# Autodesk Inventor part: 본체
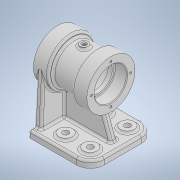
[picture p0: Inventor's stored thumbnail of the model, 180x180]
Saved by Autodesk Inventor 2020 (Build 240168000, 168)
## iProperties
Created: 2024-02
Part Number: 본체
Material: 일반
Document SubType Name: Modeling
Designer: oem
Density: 1 g/cm^3
Appearance: 기본값
Author: oem
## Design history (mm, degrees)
sketch "스케치1"
  geometry: L1 (0, 0)-(22, 0); L2 (22, 0)-(22, 35); L3 (22, 35)-(0, 35); L4 (0, 35)-(0, 0); L5 (22, 0)-(56, 0); L6 (56, 0)-(56, 28.5); L7 (56, 28.5)-(22, 28.5); L8 (22, 28.5)-(22, 0); L9 (56, 0)-(78, 0); L10 (78, 0)-(78, 35); L11 (78, 35)-(56, 35); L12 (56, 35)-(56, 0); 2 further points
  constraints: 24 end point, 6 parallel, 3 horizontal, 3 perpendicular, 1 point on line
  dimensions: "d0" = 70 diameter of L3 L1; "d1" = 57 diameter of L7 L5; "d2" = 22 distance of L2.end L3.end; "d3" = 22 distance of L10.end L11.end; "d4" = 78 distance between parallel lines of L10 L4
revolve "회전1" sketch "스케치1" stored, may be unused: angle "d5" = 90 deg
sketch "스케치2"
  geometry: L1 (0, -35)-(0, 35) reference; L2 (78, -35)-(78, 35) reference; L3 (0, 0)-(18, 0); L4 (18, 0)-(18, 23.5); L5 (18, 23.5)-(0, 23.5); L6 (0, 23.5)-(0, 0); L7 (18, 0)-(24, 0); L8 (24, 0)-(24, 20); L9 (24, 20)-(18, 20); L10 (18, 20)-(18, 0); L11 (24, 0)-(54, 0); L12 (54, 0)-(54, 23.5); L13 (54, 23.5)-(24, 23.5); L14 (24, 23.5)-(24, 0); L15 (54, 0)-(60, 0); L16 (60, 0)-(60, 20); L17 (60, 20)-(54, 20); L18 (54, 20)-(54, 0); L19 (60, 0)-(78, 0); L20 (78, 0)-(78, 23.5); L21 (78, 23.5)-(60, 23.5); L22 (60, 23.5)-(60, 0); 6 further points
  constraints: 40 end point, 10 parallel, 5 horizontal, 5 perpendicular, 3 point on line
  dimensions: "d6" = 47 diameter of L5 L3; "d7" = 40 diameter of L9 L7; "d8" = 47 diameter of L13 L11; "d9" = 18 distance of L4.end L5.end; "d10" = 18 distance of L20.end L21.end; "d11" = 24 distance between parallel lines of L8 L1; "d12" = 24 distance between parallel lines of L18 L2
revolve "회전2" sketch "스케치2" stored, may be unused: angle "d13" = 90 deg
node "작업 평면1"
sketch "스케치3"
  geometry: L1 (0, 35)-(0, -35) reference; L2 (-5, -47)-(-95, -47); L3 (-95, -47)-(-95, 47); L4 (-95, 47)-(-5, 47); L5 (-5, 47)-(-5, -47); 1 further point
  constraints: 8 end point, 2 parallel, 1 horizontal, 1 perpendicular
  dimensions: "d15" = 5 distance between parallel lines of L5 L1; "d16" = 90 distance between parallel lines of L3 L5; "d17" = 47 distance from line of L4 point (0, 0); "d18" = 94 distance of L2.end L3.end
extrude "돌출1" join sketch "스케치3" distance "d19" = 10; taper "d20" = 0 deg
sketch "스케치6"
  geometry: L1 (0, 10)-(94, 10) reference; L2 (8, 10)-(12.055, 81.969); L3 (86, 10)-(81.945, 81.969); L4 (8, 10)-(86, 10); 4 further points
  constraints: 6 end point, 2 point on line, 1 horizontal, 6 other
  dimensions: "d24" = 8 distance of L2.start L1.start; "d25" = 8 distance of L3.start L1.end
extrude "돌출2" join sketch "스케치6" distance "d26" = 10; taper "d27" = 0 deg
sketch "스케치7"
  geometry: L1 (95, -70)-(5, -70) reference; L2 (83, -70)-(66.656, -25.096); L3 (66.656, -25.096)-(13.205, -25.096); L4 (15, -35)-(15, 1.969) reference; L5 (13.205, -25.096)-(13.205, -70); 1 further point
  constraints: 6 end point, 2 perpendicular, 2 point on line
  dimensions: "d28" = 12 distance of L2.start L1.start; "d29" = 70 deg angle of L2 L1
extrude "돌출3" join sketch "스케치7" stored distance "d30" = 10; taper "d31" = 0 deg
node "작업 평면3"
  node "작업 평면2"
sketch "스케치9"
  geometry: L1 (0, 35)-(0, -35) reference; C1 r 6 at (-39, 0); 1 further point
  constraints: 1 centre point
  dimensions: "d38" = 12 diameter of C1; "d39" = 39 distance from line of C1.centre L1
extrude "돌출5" join sketch "스케치9" stored distance "d40" = 3; taper "d41" = 0 deg
sketch "스케치10"
  geometry: L1 (5, 47)-(5, -47) reference; C1 r 10 at (39, -27); C2 r 10 at (75, -27); C3 r 10 at (39, 27); C4 r 10 at (75, 27); 1 further point
  constraints: 4 centre point
  dimensions: "d42" = 20 diameter of C1; "d43" = 20 diameter of C2; "d45" = 20 diameter of C3; "d46" = 20 diameter of C4; "d47" = 34 distance from line of C1.centre L1; "d48" = 36 distance of C2.centre C1.centre; "d49" = 34 distance from line of L1 C3.centre; "d50" = 36 distance of C4.centre C3.centre; "d51" = 27 vertical distance of C4.centre point (0, 0); "d52" = 54 distance of C2.centre C4.centre; "d53" = 27 vertical distance of C3.centre point (0, 0); "d54" = 54 distance of C3.centre C1.centre
extrude "돌출6" join sketch "스케치10" distance "d55" = 3; taper "d56" = 0 deg
sketch "스케치11"
  geometry: C1 r 10 at (0, 0) reference; C2 r 10 at (0, 54) reference; C3 r 10 at (36, 54) reference; C4 r 10 at (36, 0) reference; C5 r 4.5 at (0, 0); C6 r 4.5 at (36, 0); C7 r 4.5 at (36, 54); C8 r 4.5 at (0, 54); 1 further point
  constraints: 4 centre point, 4 coincident
  dimensions: "d57" = 9 diameter of C5; "d58" = 9 diameter of C6; "d59" = 9 diameter of C7; "d60" = 9 diameter of C8
extrude "돌출7" cut sketch "스케치11" extent not by distance; stored distance "d61" = 76.124; taper "d62" = 0 deg
fillet "모깎기1" dims "d63" = 20
sketch "스케치12"
  geometry: C1 r 6 at (0, 0) reference; 2 further points
  constraints: 1 coincident
hole "구멍1" sketch "스케치12" at (0, 0) diameter "d64" = 5.1881; stored, may be unused: countersink angle "d68" = 90 deg, drill point angle "d70" = 118 deg; dims "d65" = 20, "d66" = 7, "d67" = 2, "d69" = 20
sketch "스케치13"
  geometry: C1 r 35 at (0, 0) reference; A1 r 28.5 centre (0, 0) between (0, 28.5) and (-28.5, 0); A2 r 28.5 centre (0, 0) between (5, -28.058) and (-5, -28.058) reference; 2 further points
  constraints: 4 point on circle, 1 centre point, 1 coincident
  dimensions: "d71" = 57 diameter of A1
hole "구멍2" sketch "스케치13" at (0, 28.5), (-28.5, 0), (0, -28.5), (28.5, 0) diameter "d72" = 3.242; stored, may be unused: countersink angle "d76" = 90 deg, drill point angle "d78" = 118 deg; dims "d73" = 8, "d74" = 7, "d75" = 2, "d77" = 10
node "작업 평면4"
fillet "모깎기2" dims "d79" = 1
fillet "모깎기4" dims "d81" = 3
chamfer "모따기1" distance "d83" = 1; stored, may be unused: second distance "d84" = 2, angle "d85" = 45 deg
fillet "모깎기6" dims "d86" = 3
fillet "모깎기7" dims "d87" = 3
fillet "모깎기8" dims "d88" = 3
fillet "모깎기9" dims "d89" = 3
fillet "모깎기10" dims "d90" = 3
node "솔리드1"
mirror "미러1"
feature "A9D066F2-1C7D-4E18-AEED-F7BC21143FA4" dims "d64" = 5.1881, "d65" = 20, "d66" = 7, "d67" = 2, "d68" = 90 deg, "d69" = 20, "d70" = 118 deg
other parameters: "d32" = 28.5, "d37" = 3
